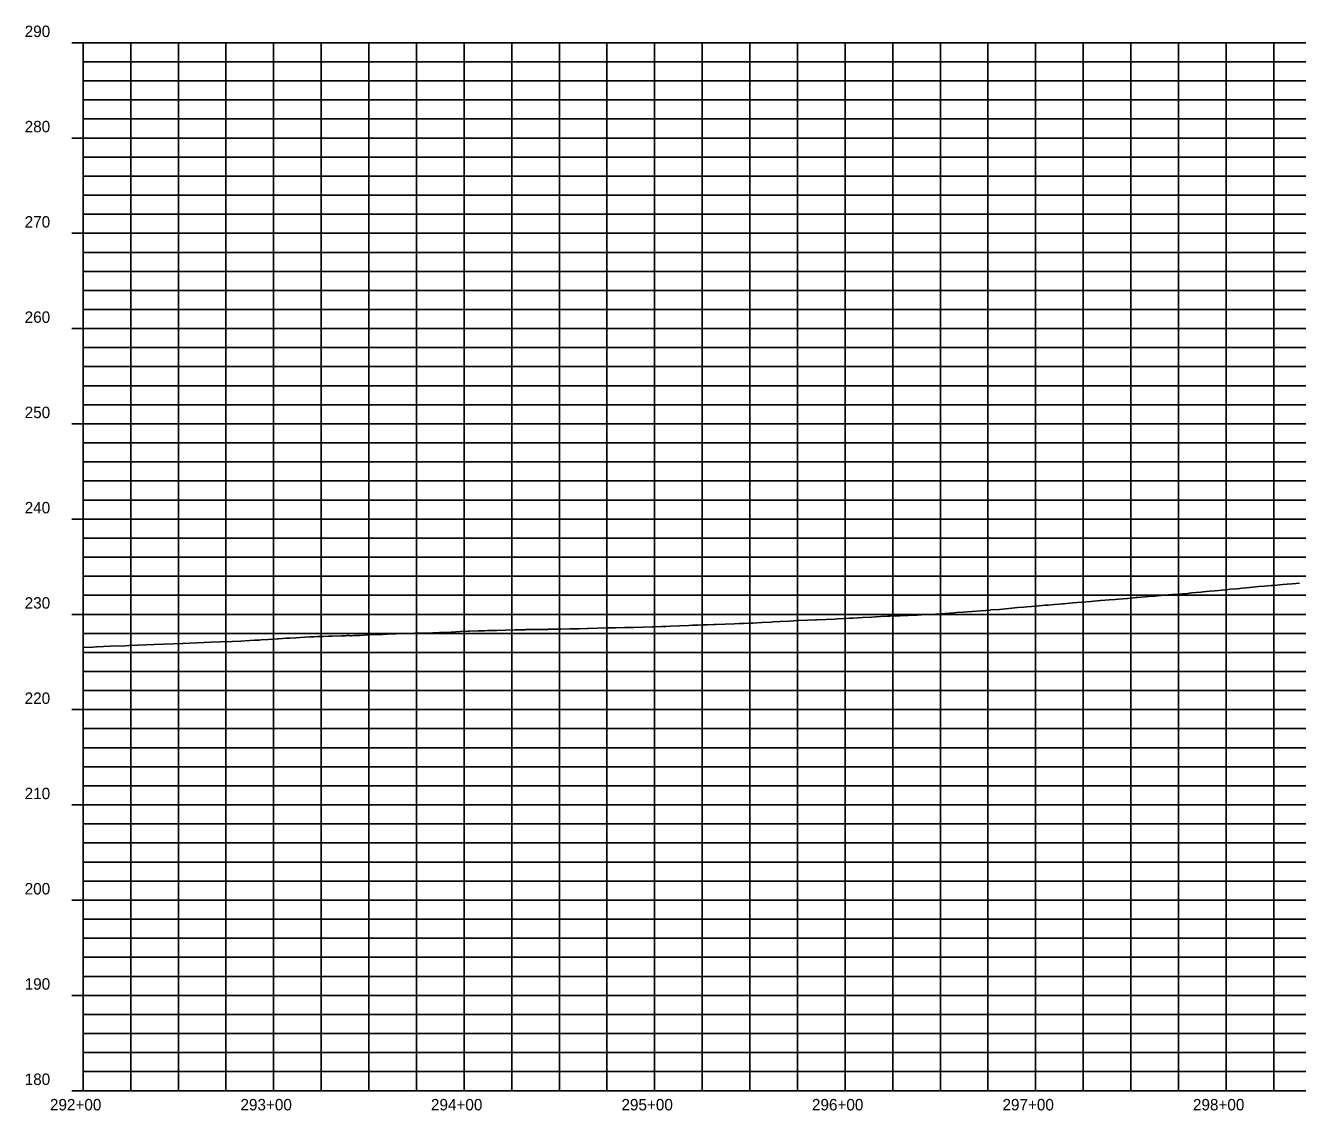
# Model space of a CAD drawing. Extents: x 921603 to 924670, y 1759276 to 1766491.
# Drawn here: x 921610 to 922277, y 1760922 to 1761491 of the extents above; entities that cross this region are included whole.
import ezdxf

# ---------------------------------------------------------------- set-up
doc = ezdxf.new("R2010")
doc.units = 0
for name, color, linetype in [('63', 7, 'Continuous'), ('R_Axis_Annotation', 7, 'Continuous'), ('R_Exist Surface', 7, 'Continuous'), ('R_Grid', 7, 'Continuous'), ('R_Grid Annot', 7, 'Continuous'), ('R_Grid_Minor', 7, 'Continuous')]:
    doc.layers.add(name, color=color, linetype=linetype)

msp = doc.modelspace()

# ---------------------------------------------------------------- linework, layer by layer
at = {"layer": 'R_Exist Surface'}
msp.add_lwpolyline([(921639.83, 1761164.78), (921644.96, 1761165.08), (921647.06, 1761165.18), (921654.05, 1761165.48), (921662.06, 1761165.8), (921663.82, 1761165.9), (921677.06, 1761166.46), (921691.99, 1761167), (921692.06, 1761167.01), (921692.16, 1761167.01), (921707.06, 1761167.68), (921711.87, 1761167.89), (921717.83, 1761168.05), (921718.29, 1761168.06), (921722.63, 1761168.27), (921727.43, 1761168.51), (921729.97, 1761168.63), (921732.23, 1761168.77), (921733.29, 1761168.84), (921737.03, 1761169.08), (921741.82, 1761169.4), (921742.41, 1761169.44), (921746.62, 1761169.72), (921748.3, 1761169.83), (921751.42, 1761170), (921756.22, 1761170.26), (921758.82, 1761170.39), (921761.02, 1761170.51), (921762.86, 1761170.6), (921763.33, 1761170.63), (921763.66, 1761170.64), (921763.9, 1761170.65), (921764.47, 1761170.66), (921765.82, 1761170.7), (921768.61, 1761170.81), (921770.62, 1761170.87), (921775.41, 1761171), (921777.55, 1761171.05), (921778.51, 1761171.11), (921779.51, 1761171.11), (921780.21, 1761171.06), (921780.69, 1761171.02), (921781.9, 1761171.12), (921784.48, 1761171.2), (921785.01, 1761171.22), (921789.81, 1761171.46), (921790.25, 1761171.48), (921794.61, 1761171.67), (921796.93, 1761171.76), (921799.41, 1761171.83), (921803.83, 1761171.95), (921804.2, 1761171.97), (921809, 1761172.17), (921811.98, 1761172.29), (921813.8, 1761172.34), (921818.6, 1761172.45), (921823.4, 1761172.57), (921824.85, 1761172.61), (921826.98, 1761172.69), (921828.06, 1761172.73), (921828.2, 1761172.73), (921833, 1761172.97), (921837.79, 1761173.21), (921841.98, 1761173.42), (921842.59, 1761173.44), (921847.39, 1761173.58), (921850.46, 1761173.67), (921852.19, 1761173.7), (921856.99, 1761173.75), (921856.99, 1761173.75), (921861.79, 1761173.91), (921866.58, 1761174.07), (921870.21, 1761174.18), (921871.12, 1761174.21), (921871.38, 1761174.21), (921871.94, 1761174.22), (921872.2, 1761174.23), (921872.21, 1761174.23), (921876.18, 1761174.29), (921880.98, 1761174.35), (921883.86, 1761174.39), (921883.94, 1761174.44), (921885.78, 1761174.43), (921889.4, 1761174.41), (921890.58, 1761174.44), (921895.29, 1761174.58), (921895.38, 1761174.58), (921900.17, 1761174.71), (921904.22, 1761174.81), (921904.97, 1761174.84), (921909.77, 1761174.98), (921914.57, 1761175.12), (921917.66, 1761175.21), (921919.37, 1761175.24), (921924.17, 1761175.33), (921926.29, 1761175.37), (921928.96, 1761175.43), (921933.76, 1761175.53), (921938.56, 1761175.63), (921939.96, 1761175.65), (921943.36, 1761175.81), (921945.68, 1761175.91), (921948.16, 1761176.03), (921952.96, 1761176.25), (921957.76, 1761176.46), (921959.67, 1761176.54), (921962.55, 1761176.65), (921965.18, 1761176.75), (921967.35, 1761176.83), (921970.88, 1761176.96), (921972.15, 1761177.01), (921976.95, 1761177.18), (921981.75, 1761177.35), (921984.22, 1761177.43), (921986.55, 1761177.5), (921990.27, 1761177.61), (921991.34, 1761177.67), (921996.14, 1761177.96), (922000.94, 1761178.23), (922002.06, 1761178.29), (922005.74, 1761178.48), (922010.54, 1761178.72), (922012.95, 1761178.83), (922015.34, 1761178.96), (922020.14, 1761179.2), (922024.29, 1761179.4), (922024.93, 1761179.42), (922029.73, 1761179.62), (922034.53, 1761179.81), (922035.69, 1761179.86), (922039.33, 1761180.05), (922042.36, 1761180.21), (922044.13, 1761180.31), (922048.91, 1761180.58), (922048.93, 1761180.58), (922053.72, 1761180.81), (922055.77, 1761180.9), (922058.52, 1761181.05), (922062.17, 1761181.23), (922063.32, 1761181.29), (922068.12, 1761181.52), (922068.68, 1761181.54), (922072.92, 1761181.71), (922075.43, 1761181.81), (922077.72, 1761181.91), (922082.29, 1761182.1), (922082.52, 1761182.11), (922087.31, 1761182.28), (922088.61, 1761182.32), (922092.11, 1761182.63), (922096.91, 1761183.05), (922098.38, 1761183.17), (922101.71, 1761183.42), (922106.35, 1761183.76), (922106.51, 1761183.78), (922111.31, 1761184.16), (922116.1, 1761184.54), (922116.22, 1761184.55), (922120.9, 1761184.87), (922124.07, 1761185.08), (922125.7, 1761185.26), (922130.5, 1761185.77), (922133.64, 1761186.09), (922135.3, 1761186.23), (922140.1, 1761186.63), (922144.9, 1761187.02), (922146.49, 1761187.15), (922149.69, 1761187.41), (922154.17, 1761187.77), (922154.49, 1761187.8), (922159.29, 1761188.23), (922164.05, 1761188.64), (922164.09, 1761188.64), (922168.89, 1761189.05), (922173.69, 1761189.45), (922174.07, 1761189.48), (922178.48, 1761189.8), (922181.59, 1761190.01), (922183.28, 1761190.18), (922188.08, 1761190.64), (922192.6, 1761191.07), (922192.88, 1761191.09), (922197.68, 1761191.49), (922200.54, 1761191.72), (922202.48, 1761191.89), (922207.28, 1761192.32), (922211.55, 1761192.7), (922212.07, 1761192.74), (922216.87, 1761193.1), (922219.47, 1761193.29), (922221.67, 1761193.5), (922226.47, 1761193.96), (922227.77, 1761194.08), (922231.27, 1761194.41), (922233.99, 1761194.67), (922236.07, 1761194.86), (922240.86, 1761195.29), (922242.21, 1761195.41), (922245.66, 1761195.72), (922248.5, 1761195.98), (922250.46, 1761196.18), (922255.26, 1761196.65), (922256.99, 1761196.82), (922260.06, 1761197.07), (922263.41, 1761197.34), (922264.86, 1761197.48), (922269.66, 1761197.93), (922271.89, 1761198.14), (922274.45, 1761198.33), (922278.3, 1761198.63)], dxfattribs=at)
at = {"layer": 'R_Grid'}
for p, q in [((921639.83, 1760932.26), (921639.83, 1761482.26)), ((921639.83, 1761482.26), (922939.83, 1761482.26)), ((921639.83, 1761482.26), (922939.83, 1761482.26)), ((921739.83, 1760932.26), (921739.83, 1761482.26)), ((921839.83, 1760932.26), (921839.83, 1761482.26)), ((921939.83, 1760932.26), (921939.83, 1761482.26)), ((922039.83, 1760932.26), (922039.83, 1761482.26)), ((922139.83, 1760932.26), (922139.83, 1761482.26)), ((922239.83, 1760932.26), (922239.83, 1761482.26)), ((921639.83, 1761432.26), (922939.83, 1761432.26)), ((921639.83, 1761382.26), (922939.83, 1761382.26)), ((921639.83, 1761332.26), (922939.83, 1761332.26)), ((921639.83, 1761282.26), (922939.83, 1761282.26)), ((921639.83, 1761232.26), (922939.83, 1761232.26)), ((921639.83, 1761182.26), (922939.83, 1761182.26)), ((921639.83, 1761132.26), (922939.83, 1761132.26)), ((921639.83, 1761082.26), (922939.83, 1761082.26)), ((921639.83, 1761032.26), (922939.83, 1761032.26)), ((921639.83, 1760982.26), (922939.83, 1760982.26)), ((921639.83, 1760932.26), (922939.83, 1760932.26))]:
    msp.add_line(p, q, dxfattribs=at)
at = {"layer": 'R_Grid Annot'}
for p, q in [((921633.83, 1761482.26), (921639.83, 1761482.26)), ((921633.83, 1761482.26), (921639.83, 1761482.26)), ((921639.83, 1761472.26), (921642.83, 1761472.26)), ((921639.83, 1761462.26), (921642.83, 1761462.26)), ((921639.83, 1761452.26), (921642.83, 1761452.26)), ((921639.83, 1761442.26), (921642.83, 1761442.26)), ((921633.83, 1761432.26), (921639.83, 1761432.26)), ((921639.83, 1761422.26), (921642.83, 1761422.26)), ((921639.83, 1761412.26), (921642.83, 1761412.26)), ((921639.83, 1761402.26), (921642.83, 1761402.26)), ((921639.83, 1761392.26), (921642.83, 1761392.26)), ((921633.83, 1761382.26), (921639.83, 1761382.26)), ((921639.83, 1761372.26), (921642.83, 1761372.26)), ((921639.83, 1761362.26), (921642.83, 1761362.26)), ((921639.83, 1761352.26), (921642.83, 1761352.26)), ((921639.83, 1761342.26), (921642.83, 1761342.26)), ((921633.83, 1761332.26), (921639.83, 1761332.26)), ((921639.83, 1761322.26), (921642.83, 1761322.26)), ((921639.83, 1761312.26), (921642.83, 1761312.26)), ((921639.83, 1761302.26), (921642.83, 1761302.26)), ((921639.83, 1761292.26), (921642.83, 1761292.26)), ((921633.83, 1761282.26), (921639.83, 1761282.26)), ((921639.83, 1761272.26), (921642.83, 1761272.26)), ((921639.83, 1761262.26), (921642.83, 1761262.26)), ((921639.83, 1761252.26), (921642.83, 1761252.26)), ((921639.83, 1761242.26), (921642.83, 1761242.26)), ((921633.83, 1761232.26), (921639.83, 1761232.26)), ((921639.83, 1761222.26), (921642.83, 1761222.26)), ((921639.83, 1761212.26), (921642.83, 1761212.26)), ((921639.83, 1761202.26), (921642.83, 1761202.26)), ((921639.83, 1761192.26), (921642.83, 1761192.26)), ((921633.83, 1761182.26), (921639.83, 1761182.26)), ((921639.83, 1761172.26), (921642.83, 1761172.26)), ((921639.83, 1761162.26), (921642.83, 1761162.26)), ((921639.83, 1761152.26), (921642.83, 1761152.26)), ((921639.83, 1761142.26), (921642.83, 1761142.26)), ((921633.83, 1761132.26), (921639.83, 1761132.26)), ((921639.83, 1761122.26), (921642.83, 1761122.26)), ((921639.83, 1761112.26), (921642.83, 1761112.26)), ((921639.83, 1761102.26), (921642.83, 1761102.26)), ((921639.83, 1761092.26), (921642.83, 1761092.26)), ((921633.83, 1761082.26), (921639.83, 1761082.26)), ((921639.83, 1761072.26), (921642.83, 1761072.26)), ((921639.83, 1761062.26), (921642.83, 1761062.26)), ((921639.83, 1761052.26), (921642.83, 1761052.26)), ((921639.83, 1761042.26), (921642.83, 1761042.26)), ((921633.83, 1761032.26), (921639.83, 1761032.26)), ((921639.83, 1761022.26), (921642.83, 1761022.26)), ((921639.83, 1761012.26), (921642.83, 1761012.26)), ((921639.83, 1761002.26), (921642.83, 1761002.26)), ((921639.83, 1760992.26), (921642.83, 1760992.26)), ((921633.83, 1760982.26), (921639.83, 1760982.26)), ((921639.83, 1760972.26), (921642.83, 1760972.26)), ((921639.83, 1760962.26), (921642.83, 1760962.26)), ((921639.83, 1760952.26), (921642.83, 1760952.26)), ((921639.83, 1760942.26), (921642.83, 1760942.26)), ((921633.83, 1760932.26), (921639.83, 1760932.26))]:
    msp.add_line(p, q, dxfattribs=at)
at = {"layer": 'R_Grid_Minor'}
for p, q in [((921664.83, 1760932.26), (921664.83, 1761482.26)), ((921689.83, 1760932.26), (921689.83, 1761482.26)), ((921714.83, 1760932.26), (921714.83, 1761482.26)), ((921764.83, 1760932.26), (921764.83, 1761482.26)), ((921789.83, 1760932.26), (921789.83, 1761482.26)), ((921814.83, 1760932.26), (921814.83, 1761482.26)), ((921864.83, 1760932.26), (921864.83, 1761482.26)), ((921889.83, 1760932.26), (921889.83, 1761482.26)), ((921914.83, 1760932.26), (921914.83, 1761482.26)), ((921964.83, 1760932.26), (921964.83, 1761482.26)), ((921989.83, 1760932.26), (921989.83, 1761482.26)), ((922014.83, 1760932.26), (922014.83, 1761482.26)), ((922064.83, 1760932.26), (922064.83, 1761482.26)), ((922089.83, 1760932.26), (922089.83, 1761482.26)), ((922114.83, 1760932.26), (922114.83, 1761482.26)), ((922164.83, 1760932.26), (922164.83, 1761482.26)), ((922189.83, 1760932.26), (922189.83, 1761482.26)), ((922214.83, 1760932.26), (922214.83, 1761482.26)), ((922264.83, 1760932.26), (922264.83, 1761482.26)), ((921639.83, 1761472.26), (922939.83, 1761472.26)), ((921639.83, 1761462.26), (922939.83, 1761462.26)), ((921639.83, 1761452.26), (922939.83, 1761452.26)), ((921639.83, 1761442.26), (922939.83, 1761442.26)), ((921639.83, 1761422.26), (922939.83, 1761422.26)), ((921639.83, 1761412.26), (922939.83, 1761412.26)), ((921639.83, 1761402.26), (922939.83, 1761402.26)), ((921639.83, 1761392.26), (922939.83, 1761392.26)), ((921639.83, 1761372.26), (922939.83, 1761372.26)), ((921639.83, 1761362.26), (922939.83, 1761362.26)), ((921639.83, 1761352.26), (922939.83, 1761352.26)), ((921639.83, 1761342.26), (922939.83, 1761342.26)), ((921639.83, 1761322.26), (922939.83, 1761322.26)), ((921639.83, 1761312.26), (922939.83, 1761312.26)), ((921639.83, 1761302.26), (922939.83, 1761302.26)), ((921639.83, 1761292.26), (922939.83, 1761292.26)), ((921639.83, 1761272.26), (922939.83, 1761272.26)), ((921639.83, 1761262.26), (922939.83, 1761262.26)), ((921639.83, 1761252.26), (922939.83, 1761252.26)), ((921639.83, 1761242.26), (922939.83, 1761242.26)), ((921639.83, 1761222.26), (922939.83, 1761222.26)), ((921639.83, 1761212.26), (922939.83, 1761212.26)), ((921639.83, 1761202.26), (922939.83, 1761202.26)), ((921639.83, 1761192.26), (922939.83, 1761192.26)), ((921639.83, 1761172.26), (922939.83, 1761172.26)), ((921639.83, 1761162.26), (922939.83, 1761162.26)), ((921639.83, 1761152.26), (922939.83, 1761152.26)), ((921639.83, 1761142.26), (922939.83, 1761142.26)), ((921639.83, 1761122.26), (922939.83, 1761122.26)), ((921639.83, 1761112.26), (922939.83, 1761112.26)), ((921639.83, 1761102.26), (922939.83, 1761102.26)), ((921639.83, 1761092.26), (922939.83, 1761092.26)), ((921639.83, 1761072.26), (922939.83, 1761072.26)), ((921639.83, 1761062.26), (922939.83, 1761062.26)), ((921639.83, 1761052.26), (922939.83, 1761052.26)), ((921639.83, 1761042.26), (922939.83, 1761042.26)), ((921639.83, 1761022.26), (922939.83, 1761022.26)), ((921639.83, 1761012.26), (922939.83, 1761012.26)), ((921639.83, 1761002.26), (922939.83, 1761002.26)), ((921639.83, 1760992.26), (922939.83, 1760992.26)), ((921639.83, 1760972.26), (922939.83, 1760972.26)), ((921639.83, 1760962.26), (922939.83, 1760962.26)), ((921639.83, 1760952.26), (922939.83, 1760952.26)), ((921639.83, 1760942.26), (922939.83, 1760942.26))]:
    msp.add_line(p, q, dxfattribs=at)

# ---------------------------------------------------------------- texts
at = {"layer": '63'}
msp.add_text('-', height=0.0001, dxfattribs=at).set_placement((921639.83, 1760932.26))
at = {"layer": 'R_Axis_Annotation'}
for s, p in [('290', (921609.16, 1761485.26)), ('290', (921609.16, 1761485.26)), ('280', (921609.16, 1761435.26)), ('270', (921609.16, 1761385.26)), ('260', (921609.16, 1761335.26)), ('250', (921609.16, 1761285.26)), ('240', (921609.16, 1761235.26)), ('230', (921609.16, 1761185.26)), ('220', (921609.16, 1761135.26)), ('210', (921609.16, 1761085.26)), ('200', (921609.16, 1761035.26)), ('190', (921609.16, 1760985.26)), ('180', (921609.16, 1760935.26)), ('292+00', (921622.42, 1760921.91)), ('293+00', (921722.42, 1760921.91)), ('294+00', (921822.42, 1760921.91)), ('295+00', (921922.42, 1760921.91)), ('296+00', (922022.42, 1760921.91)), ('297+00', (922122.42, 1760921.91)), ('298+00', (922222.42, 1760921.91))]:
    msp.add_text(s, height=6, dxfattribs=at).set_placement(p)

doc.saveas('drawing.dxf')
